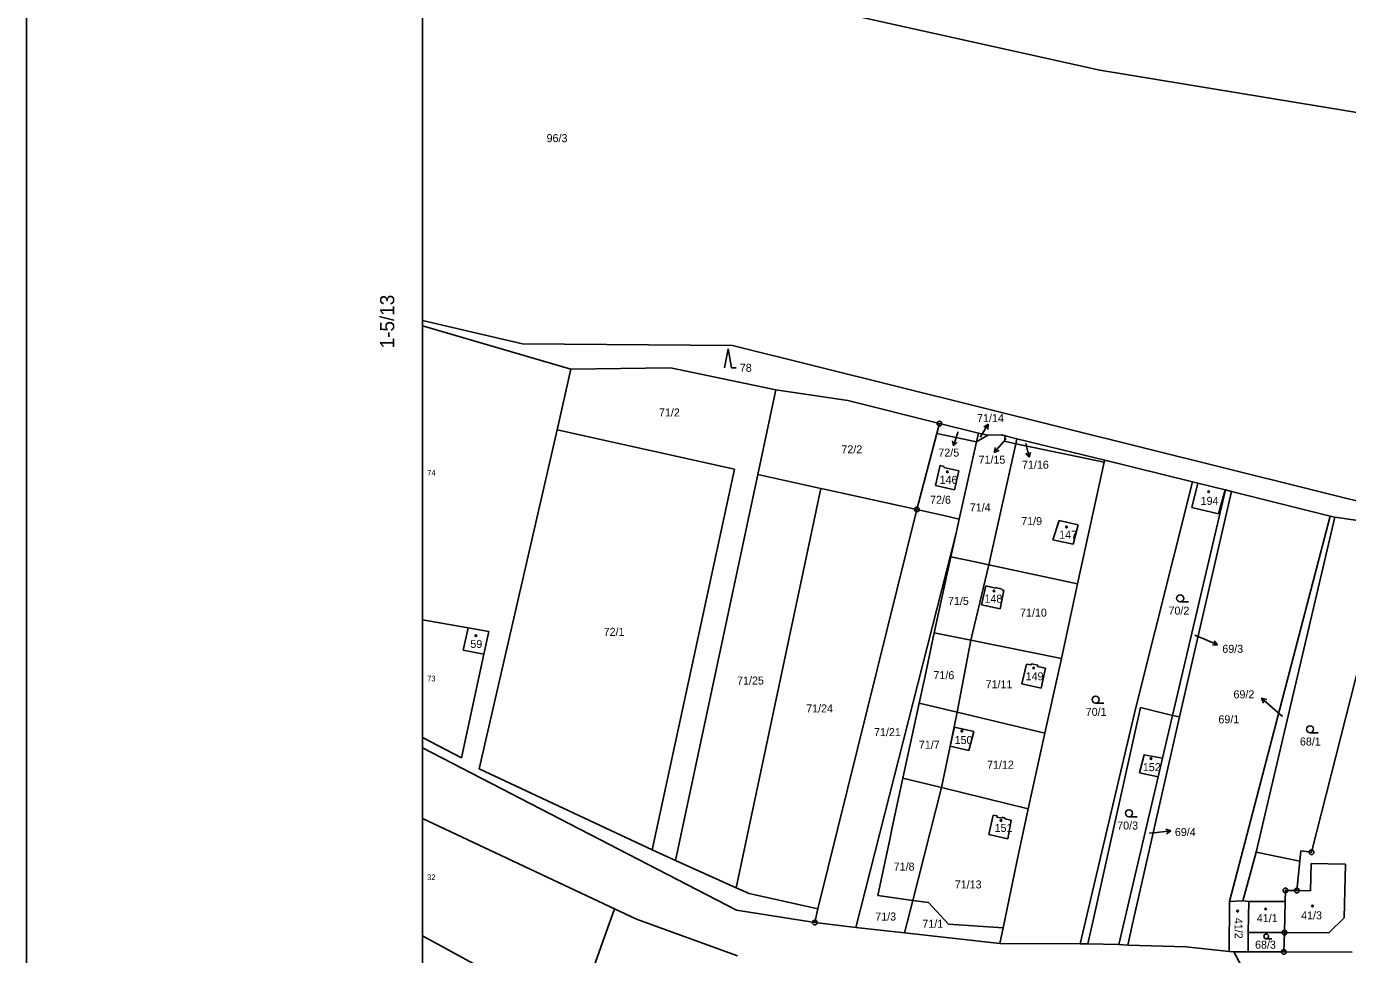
# Model space of a CAD drawing. Extents: x -654459 to -653618, y -1151040 to -1150446.
# Drawn here: x -654459.1 to -654178.6, y -1150883.2 to -1150686.2 of the extents above; entities that cross this region are included whole.
import ezdxf

# ---------------------------------------------------------------- set-up
doc = ezdxf.new("R2010")
doc.units = 0
for name, color, linetype in [('Vrstva 1', 7, 'Continuous'), ('Vrstva 13', 7, 'Continuous'), ('Vrstva 2', 7, 'Continuous'), ('Vrstva 3', 7, 'Continuous'), ('Vrstva 4', 7, 'Continuous'), ('Vrstva 5', 7, 'Continuous'), ('Vrstva 63', 7, 'Continuous'), ('Vrstva 7', 7, 'Continuous'), ('Vrstva 8', 7, 'Continuous')]:
    doc.layers.add(name, color=color, linetype=linetype)

msp = doc.modelspace()

# ---------------------------------------------------------------- linework, layer by layer
at = {"layer": 'Vrstva 1'}
for points in [[(-654231.14, -1150695.5), (-654301.35, -1150679.85)], [(-654231.14, -1150695.5), (-654155.05, -1150708)], [(-654353.76, -1150753.58), (-654375, -1150748.64)], [(-654375, -1150749.75), (-654343.52, -1150758.98)], [(-654309.16, -1150753.96), (-654353.76, -1150753.58)], [(-654309.16, -1150753.96), (-654169.59, -1150788.7)], [(-654343.52, -1150758.98), (-654346.41, -1150771.88)], [(-654322.33, -1150758.66), (-654343.52, -1150758.98)], [(-654299.93, -1150763.32), (-654322.33, -1150758.66)], [(-654303.77, -1150781.32), (-654299.93, -1150763.32)], [(-654299.93, -1150763.32), (-654284.66, -1150765.64)], [(-654284.66, -1150765.64), (-654265.21, -1150770.53)], [(-654265.21, -1150770.53), (-654265.76, -1150772.64)], [(-654265.21, -1150770.53), (-654256.92, -1150772.52)], [(-654362.99, -1150843.83), (-654346.41, -1150771.88)], [(-654346.41, -1150771.88), (-654308.73, -1150780.22)], [(-654265.76, -1150772.64), (-654269.99, -1150788.74)], [(-654265.76, -1150772.64), (-654257.33, -1150774.36)], [(-654261.02, -1150790.78), (-654257.33, -1150774.36)], [(-654257.33, -1150774.36), (-654256.92, -1150772.52)], [(-654257.33, -1150774.36), (-654254.94, -1150773)], [(-654256.92, -1150772.52), (-654254.94, -1150773)], [(-654254.94, -1150773), (-654251.97, -1150772.92)], [(-654251.97, -1150772.92), (-654251.25, -1150773.12)], [(-654251.25, -1150773.12), (-654251.39, -1150774.23)], [(-654251.39, -1150774.23), (-654248.98, -1150774.79)], [(-654251.25, -1150773.12), (-654248.75, -1150773.74)], [(-654248.98, -1150774.79), (-654248.75, -1150773.74)], [(-654248.75, -1150773.74), (-654230.13, -1150778.31)], [(-654254.7, -1150800.52), (-654248.98, -1150774.79)], [(-654248.98, -1150774.79), (-654230.22, -1150778.7)], [(-654266.03, -1150783.66), (-654265.12, -1150779.62)], [(-654265.12, -1150779.62), (-654265.08, -1150779.42)], [(-654265.08, -1150779.42), (-654264.24, -1150779.61)], [(-654264.24, -1150779.61), (-654264.29, -1150779.81)], [(-654264.29, -1150779.81), (-654261.13, -1150780.53)], [(-654235.92, -1150804.54), (-654230.22, -1150778.7)], [(-654230.22, -1150778.7), (-654230.13, -1150778.31)], [(-654230.13, -1150778.31), (-654211.51, -1150782.88)], [(-654326.2, -1150861.04), (-654308.73, -1150780.22)], [(-654303.77, -1150781.32), (-654321.28, -1150863.26)], [(-654290.38, -1150784.28), (-654303.77, -1150781.32)], [(-654261.13, -1150780.53), (-654262.05, -1150784.6)], [(-654308.4, -1150869.06), (-654290.38, -1150784.28)], [(-654289.35, -1150784.51), (-654290.38, -1150784.28)], [(-654269.99, -1150788.74), (-654289.35, -1150784.51)], [(-654262.05, -1150784.6), (-654266.03, -1150783.66)], [(-654211.51, -1150782.88), (-654223.51, -1150830.83)], [(-654215.7, -1150832.46), (-654204.48, -1150784.6)], [(-654203.22, -1150784.97), (-654214.24, -1150832.81)], [(-654210.36, -1150783.16), (-654211.6, -1150788.3)], [(-654210.36, -1150783.16), (-654211.51, -1150782.88)], [(-654204.56, -1150784.58), (-654210.36, -1150783.16)], [(-654205.93, -1150789.67), (-654204.56, -1150784.58)], [(-654204.48, -1150784.6), (-654204.56, -1150784.58)], [(-654204.48, -1150784.6), (-654203.22, -1150784.97)], [(-654203.22, -1150784.97), (-654182.28, -1150790.15)], [(-654211.6, -1150788.3), (-654205.93, -1150789.67)], [(-654291.01, -1150873.55), (-654269.99, -1150788.74)], [(-654264.32, -1150790.03), (-654269.99, -1150788.74)], [(-654261.02, -1150790.78), (-654264.32, -1150790.03)], [(-654261.02, -1150790.78), (-654261.7, -1150793.8)], [(-654239.83, -1150791.09), (-654241.14, -1150795.21)], [(-654239.83, -1150791.09), (-654235.75, -1150792)], [(-654182.28, -1150790.15), (-654203.63, -1150871.97)], [(-654197.95, -1150861.5), (-654181.23, -1150790.41)], [(-654181.23, -1150790.41), (-654182.28, -1150790.15)], [(-654168.58, -1150792.21), (-654181.23, -1150790.41)], [(-654261.7, -1150793.8), (-654282.97, -1150877.5)], [(-654262.8, -1150798.78), (-654261.7, -1150793.8)], [(-654235.75, -1150792), (-654236.84, -1150796.09)], [(-654168.58, -1150792.21), (-654186.2, -1150861.52)], [(-654241.14, -1150795.21), (-654236.84, -1150796.09)], [(-654262.8, -1150798.78), (-654264.74, -1150807.54)], [(-654257.62, -1150799.87), (-654262.8, -1150798.78)], [(-654254.7, -1150800.52), (-654258.56, -1150816.51)], [(-654254.7, -1150800.52), (-654257.62, -1150799.87)], [(-654254.7, -1150800.52), (-654235.92, -1150804.54)], [(-654255.39, -1150804.98), (-654256.28, -1150808.97)], [(-654255.39, -1150804.98), (-654253.35, -1150805.49)], [(-654239.32, -1150820.37), (-654235.92, -1150804.54)], [(-654264.74, -1150807.54), (-654266.32, -1150814.94)], [(-654253.35, -1150805.49), (-654253.3, -1150805.3)], [(-654253.3, -1150805.3), (-654251.9, -1150805.65)], [(-654251.51, -1150805.95), (-654252.29, -1150809.87)], [(-654251.9, -1150805.65), (-654251.95, -1150805.84)], [(-654251.95, -1150805.84), (-654251.51, -1150805.95)], [(-654256.28, -1150808.97), (-654252.29, -1150809.87)], [(-654375, -1150812.18), (-654365.33, -1150813.87)], [(-654366.38, -1150818.64), (-654365.33, -1150813.87)], [(-654365.33, -1150813.87), (-654360.91, -1150814.64)], [(-654361.97, -1150819.44), (-654360.91, -1150814.64)], [(-654266.32, -1150814.94), (-654268.34, -1150824.44)], [(-654266.32, -1150814.94), (-654258.56, -1150816.51)], [(-654258.56, -1150816.51), (-654261.44, -1150831.79)], [(-654239.32, -1150820.37), (-654258.56, -1150816.51)], [(-654366.38, -1150818.64), (-654361.97, -1150819.44)], [(-654366.71, -1150841.47), (-654361.97, -1150819.44)], [(-654246.76, -1150821.57), (-654247.71, -1150825.79)], [(-654246.76, -1150821.57), (-654245.74, -1150821.77)], [(-654245.74, -1150821.77), (-654245.69, -1150821.53)], [(-654245.69, -1150821.53), (-654244.36, -1150821.82)], [(-654244.36, -1150821.82), (-654244.42, -1150822.06)], [(-654244.42, -1150822.06), (-654242.69, -1150822.44)], [(-654242.85, -1150836.27), (-654239.32, -1150820.37)], [(-654268.34, -1150824.44), (-654269.51, -1150829.85)], [(-654242.69, -1150822.44), (-654243.6, -1150826.72)], [(-654247.71, -1150825.79), (-654243.6, -1150826.72)], [(-654269.51, -1150829.85), (-654272.96, -1150845.79)], [(-654261.44, -1150831.79), (-654269.51, -1150829.85)], [(-654262.97, -1150839), (-654261.44, -1150831.79)], [(-654242.85, -1150836.27), (-654261.44, -1150831.79)], [(-654223.51, -1150830.83), (-654235.37, -1150880.95)], [(-654222.55, -1150830.8), (-654232.53, -1150875.66)], [(-654214.24, -1150832.81), (-654224.35, -1150877.36)], [(-654215.7, -1150832.46), (-654222.55, -1150830.8)], [(-654217.84, -1150841.58), (-654215.7, -1150832.46)], [(-654215.7, -1150832.46), (-654214.24, -1150832.81)], [(-654262.97, -1150839), (-654261.99, -1150834.94)], [(-654261.99, -1150834.94), (-654257.94, -1150835.87)], [(-654257.94, -1150835.87), (-654258.97, -1150839.94)], [(-654366.71, -1150841.47), (-654375, -1150837.13)], [(-654246.35, -1150852.31), (-654242.85, -1150836.27)], [(-654375, -1150839.37), (-654308.34, -1150873.84)], [(-654264.79, -1150847.79), (-654262.97, -1150839)], [(-654258.97, -1150839.94), (-654262.97, -1150839)], [(-654222.73, -1150844.69), (-654221.76, -1150840.81)], [(-654221.76, -1150840.81), (-654217.84, -1150841.58)], [(-654218.78, -1150845.53), (-654217.84, -1150841.58)], [(-654362.99, -1150843.83), (-654326.2, -1150861.04)], [(-654275.23, -1150856.3), (-654272.96, -1150845.79)], [(-654272.96, -1150845.79), (-654264.79, -1150847.79)], [(-654227.12, -1150881.13), (-654218.78, -1150845.53)], [(-654222.73, -1150844.69), (-654218.78, -1150845.53)], [(-654270.86, -1150871.74), (-654264.79, -1150847.79)], [(-654264.79, -1150847.79), (-654246.35, -1150852.31)], [(-654248.75, -1150863.58), (-654246.35, -1150852.31)], [(-654375, -1150854.38), (-654334.19, -1150873.57)], [(-654254.73, -1150857.76), (-654253.79, -1150853.66)], [(-654253.79, -1150853.66), (-654252.98, -1150853.77)], [(-654252.98, -1150853.77), (-654253.05, -1150854.07)], [(-654253.05, -1150854.07), (-654251.92, -1150854.31)], [(-654251.92, -1150854.31), (-654251.88, -1150854.11)], [(-654251.88, -1150854.11), (-654251.3, -1150854.23)], [(-654251.3, -1150854.23), (-654251.34, -1150854.43)], [(-654251.34, -1150854.43), (-654249.96, -1150854.72)], [(-654249.96, -1150854.72), (-654250.73, -1150858.65)], [(-654275.69, -1150858.46), (-654278.33, -1150870.72)], [(-654275.69, -1150858.46), (-654275.23, -1150856.3)], [(-654250.73, -1150858.65), (-654254.73, -1150857.76)], [(-654321.28, -1150863.26), (-654326.2, -1150861.04)], [(-654188.49, -1150861.25), (-654188.71, -1150863.44)], [(-654188.49, -1150861.25), (-654186.2, -1150861.52)], [(-654321.28, -1150863.26), (-654308.4, -1150869.06)], [(-654251.7, -1150877.54), (-654248.75, -1150863.58)], [(-654199.66, -1150867.71), (-654197.95, -1150861.5)], [(-654188.71, -1150863.44), (-654197.95, -1150861.5)], [(-654189.34, -1150869.66), (-654188.71, -1150863.44)], [(-654186.27, -1150863.95), (-654186.43, -1150869.73)], [(-654178.98, -1150864.07), (-654186.27, -1150863.95)], [(-654178.98, -1150864.07), (-654179.26, -1150875.42)], [(-654308.4, -1150869.06), (-654305.64, -1150870.3)], [(-654200.76, -1150871.85), (-654199.66, -1150867.71)], [(-654191.81, -1150872), (-654191.75, -1150869.63)], [(-654191.75, -1150869.63), (-654189.34, -1150869.66)], [(-654186.43, -1150869.73), (-654189.34, -1150869.66)], [(-654305.64, -1150870.3), (-654291.01, -1150873.55)], [(-654278.33, -1150870.72), (-654270.86, -1150871.74)], [(-654270.86, -1150871.74), (-654272.61, -1150878.66)], [(-654270.86, -1150871.74), (-654267.56, -1150872.19)], [(-654267.56, -1150872.19), (-654263.28, -1150876.83)], [(-654203.7, -1150882.63), (-654203.63, -1150871.97)], [(-654203.63, -1150871.97), (-654200.76, -1150871.85)], [(-654199.55, -1150871.98), (-654200.76, -1150871.85)], [(-654199.65, -1150878.53), (-654199.55, -1150871.98)], [(-654191.96, -1150878.58), (-654191.81, -1150872)], [(-654342.54, -1150896.98), (-654334.19, -1150873.57)], [(-654334.19, -1150873.57), (-654329.58, -1150875.74)], [(-654308.34, -1150873.84), (-654291.69, -1150876.47)], [(-654291.01, -1150873.55), (-654291.69, -1150876.47)], [(-654182.51, -1150878.64), (-654179.26, -1150875.42)], [(-654329.58, -1150875.74), (-654308.1, -1150883.54)], [(-654282.97, -1150877.5), (-654291.69, -1150876.47)], [(-654282.97, -1150877.5), (-654272.61, -1150878.66)], [(-654263.28, -1150876.83), (-654251.7, -1150877.54)], [(-654252.42, -1150880.92), (-654251.7, -1150877.54)], [(-654232.53, -1150875.66), (-654233.71, -1150880.99)], [(-654224.35, -1150877.36), (-654225.22, -1150881.25)], [(-654375, -1150879.29), (-654342.54, -1150896.98)], [(-654272.61, -1150878.66), (-654252.42, -1150880.92)], [(-654252.42, -1150880.92), (-654235.37, -1150880.95)], [(-654235.37, -1150880.95), (-654233.71, -1150880.99)], [(-654233.71, -1150880.99), (-654227.12, -1150881.13)], [(-654199.68, -1150882.65), (-654199.65, -1150878.53)], [(-654191.96, -1150878.58), (-654199.65, -1150878.53)], [(-654192.1, -1150882.69), (-654191.96, -1150878.58)], [(-654182.51, -1150878.64), (-654191.96, -1150878.58)], [(-654225.22, -1150881.25), (-654227.12, -1150881.13)], [(-654212.82, -1150881.64), (-654225.22, -1150881.25)], [(-654212.82, -1150881.64), (-654203.7, -1150882.63)], [(-654202.69, -1150882.64), (-654203.7, -1150882.63)], [(-654199.68, -1150882.65), (-654202.69, -1150882.64)], [(-654197.94, -1150891.49), (-654202.69, -1150882.64)], [(-654192.1, -1150882.69), (-654199.68, -1150882.65)], [(-654192.1, -1150882.69), (-654177.57, -1150882.76)]]:
    msp.add_lwpolyline(points, dxfattribs=at)
at = {"layer": 'Vrstva 3'}
for p, q in [((-654310.11, -1150754.67), (-654310.86, -1150758.67)), ((-654309.36, -1150758.67), (-654310.11, -1150754.67)), ((-654309.36, -1150758.67), (-654308.36, -1150758.67)), ((-654214.1, -1150808.38), (-654212.35, -1150808.38)), ((-654232.05, -1150829.87), (-654230.3, -1150829.87)), ((-654186.52, -1150836.17), (-654184.77, -1150836.17)), ((-654224.97, -1150854), (-654223.22, -1150854)), ((-654195.82, -1150879.89), (-654194.65, -1150879.89))]:
    msp.add_line(p, q, dxfattribs=at)
for centre, radius in [((-654214.1, -1150807.63), 0.75), ((-654232.05, -1150829.12), 0.75), ((-654186.52, -1150835.42), 0.75), ((-654224.97, -1150853.25), 0.75), ((-654195.82, -1150879.39), 0.503)]:
    msp.add_circle(centre, radius, dxfattribs=at)
at = {"layer": 'Vrstva 4'}
msp.add_lwpolyline([(-654191.81, -1150872), (-654199.55, -1150871.98)], dxfattribs=at)
at = {"layer": 'Vrstva 5'}
for centre in [(-654263.54, -1150780.75), (-654208.06, -1150784.99), (-654238.23, -1150792.47), (-654253.62, -1150806.05), (-654363.66, -1150815.54), (-654245.22, -1150822.42), (-654260.45, -1150835.81), (-654220.3, -1150841.64), (-654252.16, -1150854.8), (-654201.92, -1150874.02), (-654195.96, -1150873.57), (-654185.99, -1150872.94)]:
    msp.add_circle(centre, 0.175, dxfattribs=at)
at = {"layer": 'Vrstva 63'}
msp.add_line((-654459.1, -1150445.75), (-654459.1, -1151039.75), dxfattribs=at)
msp.add_lwpolyline([(-654375, -1151000), (-653750, -1151000), (-653750, -1150500), (-654375, -1150500)], close=True, dxfattribs=at)
at = {"layer": 'Vrstva 7'}
for p, q in [((-654256.43, -1150773.22), (-654254.86, -1150770.66)), ((-654254.86, -1150770.66), (-654255.81, -1150771.25)), ((-654254.86, -1150770.66), (-654254.96, -1150771.77)), ((-654262.26, -1150775.25), (-654262.42, -1150774.15)), ((-654261.33, -1150772.4), (-654262.26, -1150775.25)), ((-654251.6, -1150774.39), (-654253.58, -1150776.65)), ((-654262.26, -1150775.25), (-654261.47, -1150774.46)), ((-654253.58, -1150776.65), (-654253.29, -1150775.57)), ((-654253.58, -1150776.65), (-654252.54, -1150776.23)), ((-654246.88, -1150774.77), (-654246.15, -1150777.68)), ((-654246.15, -1150777.68), (-654246.88, -1150776.83)), ((-654246.15, -1150777.68), (-654245.91, -1150776.59)), ((-654208.9, -1150816.3), (-654206.15, -1150817.49)), ((-654206.15, -1150817.49), (-654207.26, -1150817.55)), ((-654206.15, -1150817.49), (-654206.86, -1150816.64)), ((-654194.53, -1150830.8), (-654196.81, -1150828.84)), ((-654196.81, -1150828.84), (-654195.72, -1150829.12)), ((-654196.81, -1150828.84), (-654196.37, -1150829.88)), ((-654219.06, -1150857.3), (-654216.07, -1150856.99)), ((-654216.07, -1150856.99), (-654217.12, -1150856.6)), ((-654216.07, -1150856.99), (-654217.02, -1150857.59))]:
    msp.add_line(p, q, dxfattribs=at)
for points in [[(-654261.3, -1150772.3), (-654261.33, -1150772.4)], [(-654256.52, -1150773.37), (-654256.43, -1150773.22)], [(-654251.06, -1150773.77), (-654251.6, -1150774.39)], [(-654246.88, -1150774.76), (-654246.88, -1150774.77)], [(-654210.96, -1150815.41), (-654208.9, -1150816.3)], [(-654192.35, -1150832.68), (-654194.53, -1150830.8)], [(-654220.64, -1150857.46), (-654219.06, -1150857.3)]]:
    msp.add_lwpolyline(points, dxfattribs=at)
at = {"layer": 'Vrstva 8'}
for centre, radius in [((-654265.21, -1150770.53), 0.5), ((-654265.21, -1150770.53), 0.0303), ((-654269.99, -1150788.74), 0.5), ((-654269.99, -1150788.74), 0.0303), ((-654186.2, -1150861.52), 0.5), ((-654186.2, -1150861.52), 0.0303), ((-654191.75, -1150869.63), 0.5), ((-654191.75, -1150869.63), 0.0303), ((-654189.34, -1150869.66), 0.5), ((-654189.34, -1150869.66), 0.0303), ((-654291.69, -1150876.47), 0.5), ((-654291.69, -1150876.47), 0.0303), ((-654191.96, -1150878.58), 0.5), ((-654191.96, -1150878.58), 0.0303), ((-654192.1, -1150882.69), 0.5), ((-654192.1, -1150882.69), 0.0303)]:
    msp.add_circle(centre, radius, dxfattribs=at)

# ---------------------------------------------------------------- texts
at = {"layer": 'Vrstva 13'}
for s, p in [('146', (-654265.18, -1150783.31)), ('194', (-654209.75, -1150787.77)), ('147', (-654239.79, -1150794.96)), ('148', (-654255.65, -1150808.55)), ('59', (-654364.83, -1150818.15)), ('149', (-654246.91, -1150825.02)), ('150', (-654261.99, -1150838.54)), ('152', (-654222.03, -1150844.31)), ('151', (-654253.51, -1150857.21)), ('41/1', (-654197.82, -1150876.35)), ('41/3', (-654188.41, -1150875.77))]:
    msp.add_text(s, height=1.7, dxfattribs=at).set_placement(p)
msp.add_text('41/2', height=1.7, rotation=270.8286, dxfattribs=at).set_placement((-654202.57, -1150875.47))
at = {"layer": 'Vrstva 2'}
for s, height, p in [('96/3', 1.7, (-654348.64, -1150710.77)), ('78', 1.7, (-654307.61, -1150759.52)), ('71/2', 1.7, (-654324.78, -1150769.01)), ('72/5', 0.1, (-654261.45, -1150772.3)), ('71/14', 0.1, (-654256.66, -1150773.37)), ('71/15', 0.1, (-654251.2, -1150773.77)), ('72/2', 1.7, (-654286.04, -1150776.83)), ('71/16', 0.1, (-654247.02, -1150774.76)), ('72/6', 1.7, (-654267.21, -1150787.55)), ('71/4', 1.7, (-654258.78, -1150789.16)), ('71/9', 1.7, (-654247.85, -1150792.07)), ('71/5', 1.7, (-654263.41, -1150809.02)), ('71/10', 1.7, (-654248.1, -1150811.5)), ('70/2', 1.7, (-654216.58, -1150811.08)), ('72/1', 1.7, (-654336.53, -1150815.59)), ('69/3', 0.1, (-654211.11, -1150815.41)), ('71/25', 1.7, (-654308.19, -1150825.92)), ('71/6', 1.7, (-654266.5, -1150824.78)), ('71/11', 1.7, (-654255.42, -1150826.72)), ('71/24', 1.7, (-654293.52, -1150831.85)), ('70/1', 1.7, (-654234.16, -1150832.57)), ('69/1', 1.7, (-654205.98, -1150834.15)), ('69/2', 0.1, (-654192.5, -1150832.68)), ('71/21', 1.7, (-654279.12, -1150836.88)), ('71/7', 1.7, (-654269.59, -1150839.55)), ('68/1', 1.7, (-654188.67, -1150838.87)), ('71/12', 1.7, (-654255.11, -1150843.79)), ('70/3', 1.7, (-654227.47, -1150856.7)), ('69/4', 0.1, (-654220.78, -1150857.46)), ('71/8', 1.7, (-654274.93, -1150865.42)), ('71/13', 1.7, (-654261.96, -1150869.21)), ('71/3', 1.7, (-654278.85, -1150876.02)), ('71/1', 1.7, (-654268.85, -1150877.56)), ('68/3', 1.7, (-654198.2, -1150882))]:
    msp.add_text(s, height=height, dxfattribs=at).set_placement(p)
at = {"layer": 'Vrstva 63'}
msp.add_text('1-5/13', height=3, rotation=90, dxfattribs=at).set_placement((-654381, -1150754.55))
at = {"layer": 'Vrstva 7'}
for s, p in [('71/14', (-654257.23, -1150770.19)), ('72/5', (-654265.45, -1150777.53)), ('71/15', (-654256.92, -1150779.03)), ('71/16', (-654247.69, -1150780.1)), ('69/3', (-654205.15, -1150819.19)), ('69/2', (-654202.78, -1150828.85)), ('69/4', (-654215.22, -1150858.08))]:
    msp.add_text(s, height=1.7, dxfattribs=at).set_placement(p)
at = {"layer": 'Vrstva 8'}
for s, p in [('74', (-654374, -1150781.56)), ('73', (-654374, -1150825.25)), ('32', (-654374, -1150867.43))]:
    msp.add_text(s, height=1.19, dxfattribs=at).set_placement(p)

doc.saveas('drawing.dxf')
